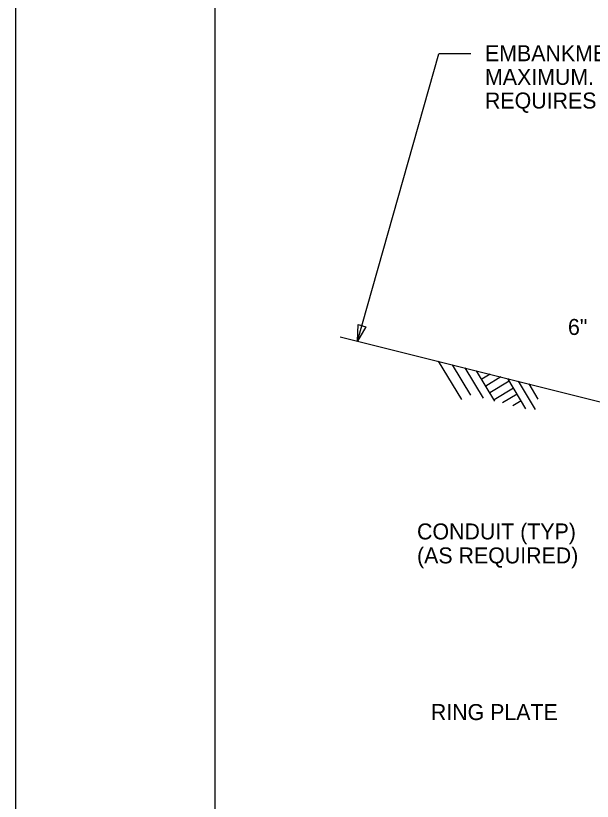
# Model space of a CAD drawing. Extents: x 1299104.6 to 1299141.4, y 239713.3 to 239735.3.
# Drawn here: x 1299104.62 to 1299108.96, y 239719.15 to 239725.05 of the extents above; entities that cross this region are included whole.
import ezdxf

# ---------------------------------------------------------------- set-up
doc = ezdxf.new("R2010")
doc.units = 0
for name, color, linetype in [('DIM TXT', 7, 'Continuous'), ('GS_plotshape_p', 7, 'Continuous'), ('Level 1', 7, 'Continuous'), ('Level 3', 7, 'Continuous'), ('Level 8', 7, 'Continuous')]:
    doc.layers.add(name, color=color, linetype=linetype)

msp = doc.modelspace()

# ---------------------------------------------------------------- linework, layer by layer
at = {"layer": 'GS_plotshape_p'}
msp.add_lwpolyline([(1299104.6223, 239735.2729), (1299138.6223, 239735.2729), (1299138.6223, 239713.2729), (1299104.6223, 239713.2729)], close=True, dxfattribs=at)
at = {"layer": 'Level 1'}
msp.add_lwpolyline([(1299138.1223, 239713.7729), (1299106.1223, 239713.7729), (1299106.1223, 239734.7729), (1299138.1223, 239734.7729)], close=True, dxfattribs=at)
at = {"layer": 'Level 3'}
msp.add_line((1299107.0626, 239722.6396), (1299109.5625, 239722.0146), dxfattribs=at)
at = {"layer": 'Level 8'}
for p, q in [((1299107.1929, 239722.607), (1299107.8049, 239724.7632)), ((1299108.0449, 239724.7632), (1299107.8049, 239724.7632)), ((1299107.9755, 239722.168), (1299107.802, 239722.4547)), ((1299108.0433, 239722.2009), (1299107.9053, 239722.4289)), ((1299108.1398, 239722.1767), (1299108.0018, 239722.4048)), ((1299108.2254, 239722.1557), (1299108.0877, 239722.3833)), ((1299108.1893, 239722.3579), (1299108.1262, 239722.3197)), ((1299108.271, 239722.3375), (1299108.1577, 239722.2689)), ((1299108.4588, 239722.0983), (1299108.3218, 239722.3248)), ((1299108.3331, 239722.3061), (1299108.1872, 239722.2178)), ((1299108.531, 239722.0931), (1299108.4031, 239722.3045)), ((1299108.5507, 239722.171), (1299108.4817, 239722.2848)), ((1299108.365, 239722.2533), (1299108.2201, 239722.1656)), ((1299108.3923, 239722.2084), (1299108.2822, 239722.1417)), ((1299108.4228, 239722.1578), (1299108.36, 239722.1197))]:
    msp.add_line(p, q, dxfattribs=at)
msp.add_lwpolyline([(1299107.2545, 239722.7143), (1299107.1929, 239722.607), (1299107.1968, 239722.7307)], close=True, dxfattribs=at)

# ---------------------------------------------------------------- texts
at = {"layer": 'DIM TXT'}
for s, p in [('EMBANKMENT SLOPE, 2:1', (1299108.1508, 239724.7086)), ('MAXIMUM. STEEPER SLOPE', (1299108.1508, 239724.531)), ('REQUIRES SPECIAL DESIGN', (1299108.1508, 239724.3533)), ('CONDUIT (TYP)', (1299107.6398, 239721.1166)), ('(AS REQUIRED)', (1299107.6398, 239720.9366)), ('RING PLATE ', (1299107.7437, 239719.7599))]:
    msp.add_text(s, height=0.12, dxfattribs=at).set_placement(p)
msp.add_text('6"', height=0.12, rotation=360, dxfattribs=at).set_placement((1299108.7746, 239722.6525))

doc.saveas('drawing.dxf')
